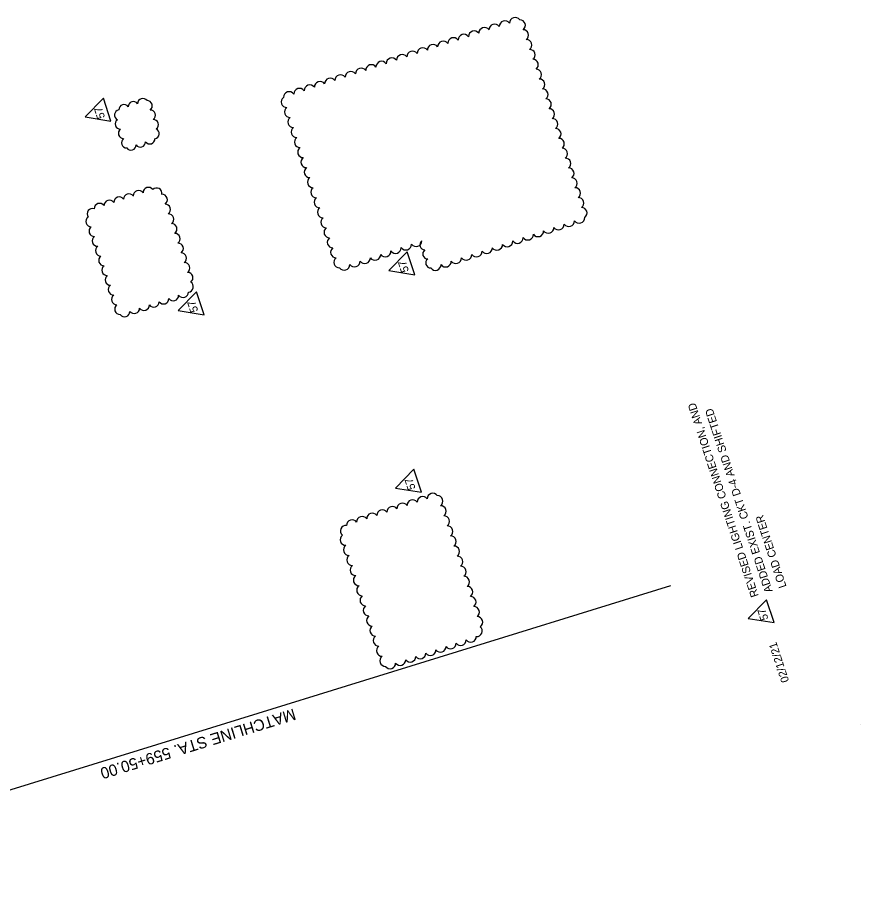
# Model space of a CAD drawing. Extents: x 929207 to 930387, y 631822 to 633132.
# Drawn here: x 929797 to 930387, y 631827 to 632437 of the extents above; entities that cross this region are included whole.
import ezdxf

# ---------------------------------------------------------------- set-up
doc = ezdxf.new("R2010")
doc.units = 0
for name, color, linetype in [('PoleLight', 7, 'Continuous'), ('TextMinor', 7, 'Continuous'), ('TextNotes', 7, 'Continuous')]:
    doc.layers.add(name, color=color, linetype=linetype)

msp = doc.modelspace()

# ---------------------------------------------------------------- linework, layer by layer
at = {"layer": 'PoleLight'}
for points in [[(929844.55, 632367.75), (929862.65, 632364.8), (929857.37, 632380.86)], [(930057.28, 632260.27), (930075.38, 632257.32), (930070.1, 632273.38)], [(929909.78, 632232.27), (929927.88, 632229.32), (929922.6, 632245.38)], [(930061.92, 632108.02), (930080.02, 632105.07), (930074.75, 632121.13)], [(930308.89, 632016.72), (930326.99, 632013.78), (930321.72, 632029.83)]]:
    msp.add_lwpolyline(points, close=True, dxfattribs=at)
for centre, radius, start, end in [((930138.52, 632431.03), 3.97, 35.68663, 180.68663), ((930145.71, 632433.39), 3.97, 35.68663, 180.68663), ((930148.98, 632431.89), 3.82, 305.68663, 90.68663), ((930116.94, 632423.94), 3.97, 35.68663, 180.68663), ((930124.13, 632426.3), 3.97, 35.68663, 180.68663), ((930131.32, 632428.66), 3.97, 35.68663, 180.68663), ((930151.25, 632424.98), 3.82, 305.68663, 90.68663), ((930102.55, 632419.21), 3.97, 35.68663, 180.68663), ((930109.75, 632421.58), 3.97, 35.68663, 180.68663), ((930153.52, 632418.06), 3.82, 305.68663, 90.68663), ((930080.98, 632412.12), 3.97, 35.68663, 180.68663), ((930088.17, 632414.49), 3.97, 35.68663, 180.68663), ((930095.36, 632416.85), 3.97, 35.68663, 180.68663), ((930066.59, 632407.4), 3.97, 35.68663, 180.68663), ((930073.79, 632409.76), 3.97, 35.68663, 180.68663), ((930155.79, 632411.15), 3.82, 305.68663, 90.68663), ((930045.02, 632400.31), 3.97, 35.68663, 180.68663), ((930052.21, 632402.67), 3.97, 35.68663, 180.68663), ((930059.4, 632405.04), 3.97, 35.68663, 180.68663), ((930158.06, 632404.23), 3.82, 305.68663, 90.68663), ((930023.44, 632393.22), 3.97, 35.68663, 180.68663), ((930030.63, 632395.58), 3.97, 35.68663, 180.68663), ((930037.82, 632397.95), 3.97, 35.68663, 180.68663), ((930160.33, 632397.32), 3.82, 305.68663, 90.68663), ((930009.06, 632388.5), 3.97, 35.68663, 180.68663), ((930016.25, 632390.86), 3.97, 35.68663, 180.68663), ((930162.61, 632390.41), 3.82, 305.68663, 90.68663), ((929987.48, 632381.41), 3.97, 35.68663, 180.68663), ((929994.67, 632383.77), 3.97, 35.68663, 180.68663), ((930001.86, 632386.13), 3.97, 35.68663, 180.68663), ((930164.88, 632383.49), 3.82, 305.68663, 90.68663), ((929884.99, 632377.03), 3.64, 35.68663, 180.68663), ((929887.99, 632375.51), 3.64, 305.68663, 90.68663), ((929985.77, 632378.21), 3.87, 125.68663, 270.68663), ((930167.15, 632376.58), 3.82, 305.68663, 90.68663), ((929868.8, 632369.07), 3.63, 99.75168, 244.75168), ((929871.82, 632372.7), 3.64, 35.68663, 180.68663), ((929878.4, 632374.86), 3.64, 35.68663, 180.68663), ((929890.15, 632368.92), 3.64, 305.68663, 90.68663), ((929988.07, 632371.2), 3.87, 125.68663, 270.68663), ((930169.42, 632369.66), 3.82, 305.68663, 90.68663), ((929990.38, 632364.18), 3.87, 125.68663, 270.68663), ((930171.69, 632362.75), 3.82, 305.68663, 90.68663), ((929869.37, 632362.83), 3.64, 125.68663, 270.68663), ((929892.32, 632362.33), 3.64, 305.68663, 90.68663), ((929992.68, 632357.16), 3.87, 125.68663, 270.68663), ((929871.53, 632356.24), 3.64, 125.68663, 270.68663), ((929892.89, 632356.09), 3.63, 279.75168, 64.75168), ((930173.96, 632355.84), 3.82, 305.68663, 90.68663), ((929873.69, 632349.65), 3.64, 125.68663, 270.68663), ((929876.69, 632348.14), 3.64, 215.68663, 0.68663), ((929883.28, 632350.3), 3.64, 215.68663, 0.68663), ((929889.87, 632352.47), 3.64, 215.68663, 0.68663), ((929994.99, 632350.15), 3.87, 125.68663, 270.68663), ((930176.24, 632348.92), 3.82, 305.68663, 90.68663), ((929997.3, 632343.13), 3.87, 125.68663, 270.68663), ((930178.51, 632342.01), 3.82, 305.68663, 90.68663), ((929999.6, 632336.11), 3.87, 125.68663, 270.68663), ((930180.78, 632335.09), 3.82, 305.68663, 90.68663), ((930001.91, 632329.09), 3.87, 125.68663, 270.68663), ((930183.05, 632328.18), 3.82, 305.68663, 90.68663), ((930004.21, 632322.08), 3.87, 125.68663, 270.68663), ((930185.32, 632321.26), 3.82, 305.68663, 90.68663), ((929888.93, 632314.68), 3.77, 35.68663, 180.68663), ((929894.65, 632314.21), 3.77, 349.97199, 134.97199), ((930006.52, 632315.06), 3.87, 125.68663, 270.68663), ((930187.59, 632314.35), 3.82, 305.68663, 90.68663), ((929868.45, 632307.95), 3.77, 35.68663, 180.68663), ((929875.27, 632310.19), 3.77, 35.68663, 180.68663), ((929882.1, 632312.43), 3.77, 35.68663, 180.68663), ((929898.4, 632309.79), 3.77, 305.68663, 90.68663), ((929854.79, 632303.46), 3.77, 35.68663, 180.68663), ((929861.62, 632305.7), 3.77, 35.68663, 180.68663), ((929900.64, 632302.96), 3.77, 305.68663, 90.68663), ((930008.82, 632308.04), 3.87, 125.68663, 270.68663), ((930189.86, 632307.44), 3.82, 305.68663, 90.68663), ((929849.77, 632299.87), 3.76, 70.46585, 215.46585), ((929902.89, 632296.13), 3.77, 305.68663, 90.68663), ((930011.13, 632301.02), 3.87, 125.68663, 270.68663), ((930192.14, 632300.52), 3.82, 305.68663, 90.68663), ((929848.9, 632294.63), 3.77, 125.68663, 270.68663), ((930013.43, 632294.01), 3.87, 125.68663, 270.68663), ((930183.21, 632295.02), 3.97, 215.68663, 0.68663), ((930190.4, 632297.38), 3.97, 215.68663, 0.68663), ((929851.14, 632287.8), 3.77, 125.68663, 270.68663), ((929905.13, 632289.31), 3.77, 305.68663, 90.68663), ((930015.74, 632286.99), 3.87, 125.68663, 270.68663), ((930161.65, 632287.93), 3.97, 215.68663, 0.68663), ((930168.84, 632290.29), 3.97, 215.68663, 0.68663), ((930176.02, 632292.65), 3.97, 215.68663, 0.68663), ((929853.38, 632280.97), 3.77, 125.68663, 270.68663), ((929907.37, 632282.48), 3.77, 305.68663, 90.68663), ((930018.04, 632279.97), 3.87, 125.68663, 270.68663), ((930076.36, 632280.95), 3.98, 215.68663, 0.68663), ((930082.37, 632278.16), 3.49, 125.68663, 270.68663), ((930140.09, 632280.85), 3.97, 215.68663, 0.68663), ((930147.28, 632283.21), 3.97, 215.68663, 0.68663), ((930154.47, 632285.57), 3.97, 215.68663, 0.68663), ((929855.63, 632274.15), 3.77, 125.68663, 270.68663), ((929909.61, 632275.65), 3.77, 305.68663, 90.68663), ((930020.35, 632272.96), 3.87, 125.68663, 270.68663), ((930061.95, 632276.22), 3.98, 215.68663, 0.68663), ((930069.15, 632278.59), 3.98, 215.68663, 0.68663), ((930125.72, 632276.13), 3.97, 215.68663, 0.68663), ((930132.91, 632278.49), 3.97, 215.68663, 0.68663), ((929857.87, 632267.32), 3.77, 125.68663, 270.68663), ((929911.86, 632268.83), 3.77, 305.68663, 90.68663), ((930022.65, 632265.94), 3.87, 125.68663, 270.68663), ((930040.34, 632269.12), 3.98, 215.68663, 0.68663), ((930047.54, 632271.49), 3.98, 215.68663, 0.68663), ((930054.75, 632273.85), 3.98, 215.68663, 0.68663), ((930084.45, 632271.83), 3.49, 125.68663, 270.68663), ((930104.16, 632269.05), 3.97, 215.68663, 0.68663), ((930111.35, 632271.41), 3.97, 215.68663, 0.68663), ((930118.54, 632273.77), 3.97, 215.68663, 0.68663), ((929860.11, 632260.49), 3.77, 125.68663, 270.68663), ((929914.1, 632262), 3.77, 305.68663, 90.68663), ((930025.93, 632264.39), 3.98, 215.68663, 0.68663), ((930033.13, 632266.75), 3.98, 215.68663, 0.68663), ((930086.53, 632265.5), 3.49, 125.68663, 270.68663), ((930089.79, 632264.33), 3.97, 215.68663, 0.68663), ((930096.98, 632266.69), 3.97, 215.68663, 0.68663), ((929862.36, 632253.67), 3.77, 125.68663, 270.68663), ((929916.34, 632255.17), 3.77, 305.68663, 90.68663), ((929916.62, 632248.87), 3.76, 274.41201, 59.41201), ((929864.6, 632246.84), 3.77, 125.68663, 270.68663), ((929913.15, 632245.07), 3.77, 215.68663, 0.68663), ((929866.84, 632240.01), 3.77, 125.68663, 270.68663), ((929892.67, 632238.35), 3.77, 215.68663, 0.68663), ((929899.49, 632240.59), 3.77, 215.68663, 0.68663), ((929906.32, 632242.83), 3.77, 215.68663, 0.68663), ((929869.08, 632233.19), 3.77, 125.68663, 270.68663), ((929879.01, 632233.86), 3.77, 215.68663, 0.68663), ((929885.84, 632236.1), 3.77, 215.68663, 0.68663), ((929872.19, 632231.62), 3.77, 215.68663, 0.68663), ((930087.97, 632100.43), 3.9, 35.68663, 180.68663), ((930073.86, 632095.79), 3.9, 35.68663, 180.68663), ((930080.92, 632098.11), 3.9, 35.68663, 180.68663), ((930091.19, 632098.8), 3.9, 305.68663, 90.68663), ((930052.68, 632088.83), 3.9, 35.68663, 180.68663), ((930059.74, 632091.15), 3.9, 35.68663, 180.68663), ((930066.8, 632093.47), 3.9, 35.68663, 180.68663), ((930093.5, 632091.74), 3.9, 305.68663, 90.68663), ((930031.5, 632081.87), 3.9, 35.68663, 180.68663), ((930038.56, 632084.19), 3.9, 35.68663, 180.68663), ((930045.62, 632086.51), 3.9, 35.68663, 180.68663), ((930095.82, 632084.68), 3.9, 305.68663, 90.68663), ((930027.27, 632077.95), 3.89, 84.99801, 229.99801), ((930098.14, 632077.63), 3.9, 305.68663, 90.68663), ((930027.04, 632071.8), 3.9, 125.68663, 270.68663), ((930100.46, 632070.57), 3.9, 305.68663, 90.68663), ((930029.35, 632064.74), 3.9, 125.68663, 270.68663), ((930102.78, 632063.51), 3.9, 305.68663, 90.68663), ((930031.67, 632057.68), 3.9, 125.68663, 270.68663), ((930105.1, 632056.45), 3.9, 305.68663, 90.68663), ((930033.99, 632050.62), 3.9, 125.68663, 270.68663), ((930107.42, 632049.39), 3.9, 305.68663, 90.68663), ((930036.31, 632043.56), 3.9, 125.68663, 270.68663), ((930109.74, 632042.33), 3.9, 305.68663, 90.68663), ((930038.63, 632036.5), 3.9, 125.68663, 270.68663), ((930112.06, 632035.27), 3.9, 305.68663, 90.68663), ((930040.95, 632029.44), 3.9, 125.68663, 270.68663), ((930114.38, 632028.21), 3.9, 305.68663, 90.68663), ((930043.27, 632022.39), 3.9, 125.68663, 270.68663), ((930116.7, 632021.15), 3.9, 305.68663, 90.68663), ((930045.59, 632015.33), 3.9, 125.68663, 270.68663), ((930119.02, 632014.09), 3.9, 305.68663, 90.68663), ((930047.91, 632008.27), 3.9, 125.68663, 270.68663), ((930118.78, 632007.95), 3.89, 264.99801, 49.99801), ((930050.23, 632001.21), 3.9, 125.68663, 270.68663), ((930107.49, 632001.7), 3.9, 215.68663, 0.68663), ((930114.55, 632004.02), 3.9, 215.68663, 0.68663), ((930052.55, 631994.15), 3.9, 125.68663, 270.68663), ((930086.31, 631994.74), 3.9, 215.68663, 0.68663), ((930093.37, 631997.06), 3.9, 215.68663, 0.68663), ((930100.43, 631999.38), 3.9, 215.68663, 0.68663), ((930054.87, 631987.09), 3.9, 125.68663, 270.68663), ((930072.19, 631990.1), 3.9, 215.68663, 0.68663), ((930079.25, 631992.42), 3.9, 215.68663, 0.68663), ((930058.08, 631985.47), 3.9, 215.68663, 0.68663), ((930065.14, 631987.79), 3.9, 215.68663, 0.68663)]:
    msp.add_arc(centre, radius, start, end, dxfattribs=at)
at = {"layer": 'TextMinor'}
msp.add_lwpolyline([(930254.51, 632039.52), (929910.55, 631933.25), (929566.59, 631826.98)], dxfattribs=at)
at = {"layer": 'TextNotes'}
msp.add_line((930387.47, 631942.57), (930387.47, 631942.57), dxfattribs=at)

# ---------------------------------------------------------------- texts
at = {"layer": 'PoleLight'}
for s, p in [('57', (929858.66, 632367.41)), ('57', (930071.39, 632259.93)), ('57', (929923.89, 632231.93)), ('REVISED LIGHTING CONNECTION, AND ', (930316.22, 632032.62)), ('ADDED EXIST. CKT D-4 AND SHIFTED ', (930325.97, 632035.83)), ('57', (930076.03, 632107.68)), ('LOAD CENTER', (930335.72, 632039.03)), ('57', (930323.01, 632016.38)), ('02/12/21', (930337.54, 631972.95))]:
    msp.add_text(s, height=5.6, rotation=108.18663, dxfattribs=at).set_placement(p)
at = {"layer": 'TextMinor'}
msp.add_text('MATCHLINE STA. 559+50.00', height=8, rotation=197.16944, dxfattribs=at).set_placement((929990.56, 631953.78))

doc.saveas('drawing.dxf')
